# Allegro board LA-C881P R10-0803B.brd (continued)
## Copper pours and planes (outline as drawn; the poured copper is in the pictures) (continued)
B+ on TOP: 171.81,37.04 171.81,35.9 172.07,35.64 173.38,35.64 174.85,37.11 174.85,39.07 174.6,39.33 172.95,39.33 172.82,39.2 172.82,38.31 172.95,38.19 172.95,37.55 172.57,37.17 171.93,37.17
B+ on BOTTOM: 62.22,62.57 63.22,62.57 63.73,62.06 63.73,59.58 64.11,59.2 64.11,57.74 60.17,53.81 60.17,52.54 58.65,51.01 55.22,51.01 54.97,51.27 54.97,53.3 55.09,53.43 55.98,53.43 56.24,53.68 57.76,53.68 58.01,53.93 58.01,56.85 58.52,57.36 59.41,57.36 60.3,58.25 61.82,58.25 62.08,58.51 62.08,62.43
B+ on BOTTOM: 203.68,78.95 204.57,78.95 204.7,79.08 204.7,80.22 204.45,80.48 203.81,80.48 203.56,80.22 203.56,79.08
B+ on BOTTOM: 79.99,31.2 79.86,31.33 79.86,34.76 80.75,35.65 81.76,35.65 82.27,36.15 84.05,36.15 84.94,37.04 84.94,37.42 85.7,38.19 86.59,38.19 86.72,38.06 86.72,37.17 86.59,37.04 86.34,37.04 84.43,35.14 82.78,35.14 81.26,33.61 81.26,31.33 81.13,31.2
B+ on IN2: 65.38,52.03 65.38,50.89 72.87,43.39 72.87,40.6 78.97,34.5 80.49,34.5 81.13,33.87 81.13,31.33 80.62,30.82 76.68,30.82 70.21,37.3 60.43,37.3 53.95,43.77 53.95,50.5 55.09,51.65 55.09,52.54 58.52,55.97 59.41,55.97 59.67,55.71 59.67,53.04 60.3,52.41 65,52.41
B+ on IN2: 195.17,14.94 189.33,14.94 188.13,16.15 184.13,16.15 180.32,19.96 179.24,19.96 178.73,19.45 176.44,19.45 175.74,20.15 175.74,21.93 176,22.18 185.46,22.18 187.11,20.53 191.05,20.53 192.95,18.63 195.43,18.63 195.68,18.37 195.68,15.45
B+ on IN2: 173.08,35.52 173.71,35.52 174.09,35.9 174.09,36.41 174.35,36.66 174.73,36.66 174.98,36.92 174.98,37.42 175.87,38.31 175.87,43.27 176.89,44.28 180.19,44.28 181.33,45.42 181.33,51.39 180.57,52.16 179.05,52.16 177.83,50.94 177.83,47.15 178.03,46.95 178.03,46.31 177.78,46.06 175.16,46.06 173.53,44.43 173.53,39.66 172.7,38.82 172.7,35.9
B+ on IN3: outline of 87 points within 159.61,15.83 176.63,37.7
B+ on IN3: 69.57,41.87 81.51,41.87 84.24,39.13 84.24,37.87 87.46,34.65 88.73,34.65 93.45,29.93 93.45,28.15 93.57,28.03 93.57,23.58 95.99,21.17 95.99,17.48 95.73,17.23 94.84,17.23 94.46,16.85 83.29,16.85 80.62,19.52 80.62,30.18 80.18,30.63 76.49,30.63 69.44,37.68 69.44,41.74
B+ on IN3: 191.49,50.76 193.42,52.69 196.22,52.69 196.95,53.43 196.95,61.3 196.44,61.81 196.44,74.51 196.95,75.02 198.48,75.02 199.24,74.25 199.24,52.41 198.25,51.42 193.98,51.42 190.53,47.96 188.7,47.96 187.81,48.85 182.22,48.85 180.82,50.25 180.44,50.25 179.55,51.14 179.55,51.77 180.06,52.28 181.46,52.28 182.6,51.14 188.57,51.14 188.95,50.76
B+ on IN4: 100.12,18.42 163.09,18.42 163.42,18.08 163.42,17.55 161.67,15.8 92.97,15.8 92.61,16.16 92.61,17.33 93.15,17.87 99.56,17.87
B+ on GND3: 166.07,14.44 165.56,14.94 100.92,14.94 99.65,16.21 93.68,16.21 93.19,16.7 93.19,18.01 94.44,19.26 99.82,19.26 101.09,17.99 115.9,17.99 116.41,18.5 117.09,18.5 117.6,17.99 163.19,17.99 163.45,17.74 164.16,17.74 164.42,17.99 174.75,17.99 175.11,17.63 175.11,15.56 174.49,14.94 166.75,14.94 166.24,14.44
B+_1.0V on TOP: 197.52,64.29 197.59,64.22 197.59,63.33 197.46,63.2 196.19,63.2 195.68,62.7 194.29,62.7 194.03,62.95 194.03,64.22 194.1,64.29
B+_1.0V on BOTTOM: 200.1,64.86 200.1,63.99 198.12,63.99 197.33,63.2 196.57,63.2 196.06,62.7 194.21,62.7 194.03,62.87 194.03,64.6 194.29,64.86 195.58,64.86 195.58,65.24 196.09,65.74 197.43,65.74 198.32,64.86
B+_3V on TOP (solid shape): 94.21,24.09 94.21,22.44 93.93,22.16 92.35,22.16 91.89,22.62 91.38,22.62 90.94,22.18 89.48,22.18 89.48,22.72 89.13,23.07 89.13,23.58 89.76,24.22 94.08,24.22
B+_3V on BOTTOM: 93.86,24.44 94.21,24.09 94.21,22.44 93.93,22.16 92.35,22.16 91.82,22.69 91.24,22.69 90.8,22.25 90.8,21.93 90.74,21.87 89.27,21.87 89.2,21.93 89.2,23 89.13,23.07 89.13,23.32 90.25,24.44
B+_3V on IN2: 92.3,22.56 89.13,22.56 88.88,22.82 88.88,23.33 89.13,23.58 89.64,23.58 90.27,24.22 92.3,24.22 92.43,24.09 92.43,22.69
B+_5V on TOP: 62.97,44.03 63.09,43.9 64.62,43.9 65.13,43.39 69.3,43.39 69.41,43.49 69.41,43.77 69.52,43.89 71.1,43.89 71.22,44.01 71.22,44.92 70.97,45.17 63.22,45.17 62.97,44.92
B+_5V on BOTTOM: 62.91,44.42 62.91,43.65 62.98,43.58 64.55,43.58 64.75,43.77 65.63,43.77 66.02,43.39 69.28,43.39 69.43,43.54 69.43,43.77 69.52,43.86 71.06,43.86 71.22,44.03 71.22,44.92 70.97,45.17 67.41,45.17 67.16,45.42 63.02,45.42 62.84,45.25 62.84,44.49
BATBTN# on TOP: 3.02,24.47 4.55,24.47 4.67,24.34 4.67,21.68 4.29,21.29 4.29,20.53 4.42,20.41 5.44,20.41 5.56,20.28 5.56,18.5 5.44,18.37 3.02,18.37 2.77,18.63 2.77,21.04 2.9,21.17 2.9,24.34
BQ24777_REGN on BOTTOM: 44.69,29.81 44.93,30.06 44.93,31.2 45.82,32.09 45.82,32.6 45.95,32.72 46.97,32.72 47.09,32.6 47.09,32.34 46.71,31.96 46.71,30.82 46.46,30.57 45.57,30.57 45.31,30.31 45.31,30.06 44.87,29.61 43.36,29.61 43.31,29.66 43.31,29.77 43.35,29.81
BST_3V on BOTTOM (solid shape): 89.03,23.23 89.03,21.95 88.95,21.88 88.8,21.88 88.62,22.06 87.86,22.06 87.73,22.18 87.73,23.08 88.06,23.4 88.85,23.4
BST_5V on BOTTOM: 62.71,43.66 62.71,45.24 62.58,45.37 62.06,45.37 61.95,45.26 61.95,43.77 62.14,43.58 62.64,43.58
CHAGER_SRC on TOP: 51.16,36.66 51.28,36.53 51.28,35.77 51.54,35.52 51.54,30.18 52.05,29.68 55.22,29.68 55.35,29.55 55.35,25.74 54.59,24.98 50.65,24.98 50.52,25.1 50.52,30.69 50.39,30.82 50.39,32.85 50.14,33.11 48.36,33.11 48.11,33.36 48.11,35.9 48.39,36.18 49.35,36.18 49.84,36.66
CHAGER_SRC on BOTTOM: 50.78,36.66 50.9,36.53 50.9,35.9 51.03,35.77 51.28,35.77 51.54,35.52 51.54,30.18 52.05,29.68 55.22,29.68 55.35,29.55 55.35,25.74 54.59,24.98 50.65,24.98 50.52,25.1 50.52,30.69 50.39,30.82 50.39,32.85 50.14,33.11 48.36,33.11 48.11,33.36 48.11,36.41 48.36,36.66
CHG_BTS on BOTTOM (solid shape): 46.33,30.18 46.33,29.42 46.2,29.3 44.43,29.3 44.33,29.2 44.05,29.2 44.05,29.2 43.37,29.2 43.3,29.27 43.3,29.36 43.37,29.42 44.3,29.42 44.43,29.55 45.06,29.55 45.63,30.12 45.63,30.25 46.27,30.25
CHG_LGATE on BOTTOM: 43.32,30.22 44.21,30.22 44.3,30.31 44.3,30.95 44.43,31.07 44.68,31.07 44.81,30.95 44.81,30.13 44.6,29.93 44.25,29.93 44.19,30 43.62,30 43.61,29.99 43.31,29.99 43.28,30.02 43.28,30.18
CHG_LGATE on BOTTOM: 53.7,33.36 54.59,33.36 54.84,33.61 54.84,34.38 54.71,34.5 53.57,34.5 53.44,34.38 53.44,33.61
CHG_LGATE on IN1: 44.3,30.06 44.3,31.2 44.68,31.58 45.7,31.58 45.95,31.33 45.95,31.07 45.57,30.69 44.93,30.69 44.81,30.57 44.81,30.06 44.68,29.93 44.43,29.93
CHG_LGATE on IN1: 53.7,34.5 54.59,34.5 54.84,34.25 54.84,32.98 54.71,32.85 53.95,32.85 53.57,33.23 53.57,34.38
CHG_SW on BOTTOM (solid shape): 61.44,34.88 61.44,30.69 60.43,29.68 58.78,29.68 57.89,28.79 57.89,26.88 57.63,26.63 56.11,26.63 55.86,26.88 55.86,30.57 55.09,31.33 55.09,33.87 55.98,34.76 55.98,36.28 56.24,36.53 59.79,36.53
CHG_SW on BOTTOM: 43.36,28.61 44.34,28.61 44.43,28.53 45.44,28.53 45.57,28.66 45.57,28.91 45.7,29.04 46.71,29.04 46.84,28.91 46.84,28.08 46.76,28 46.4,28 46.3,27.9 44.68,27.9 44.43,28.15 44.43,28.28 44.3,28.41 43.36,28.41 43.31,28.46 43.31,28.56
CHG_SW on IN1: 47.73,28.79 47.73,28.15 47.47,27.9 46.33,27.9 46.08,28.15 46.08,28.91 46.2,29.04 47.47,29.04
CHG_SW on IN1: 58.65,34.76 58.52,34.63 57.89,34.63 57.63,34.88 57.63,36.25 57.78,36.4 58.53,36.4 58.65,36.27
CHG_UGATE on BOTTOM: 44.45,29.17 45.31,29.17 45.44,29.04 45.44,28.79 45.31,28.66 44.48,28.66 44.35,28.79 43.35,28.79 43.31,28.83 43.31,28.99 43.33,29.02 44.3,29.02
CHG_UGATE on BOTTOM: 57.13,26.12 56.24,26.12 55.98,25.87 55.98,24.85 56.11,24.72 57.25,24.72 57.38,24.85 57.38,25.87
CHG_UGATE on IN4: 44.43,28.66 45.31,28.66 45.44,28.79 45.44,28.91 45.7,29.17 46.2,29.17 46.46,29.42 46.46,30.18 46.33,30.31 45.31,30.31 44.3,29.3 44.3,28.79
CHG_UGATE on IN4: 57.25,24.72 57.38,24.85 57.38,25.49 56.79,26.08 54.82,26.08 54.5,25.76 54.5,25.05 54.83,24.72
CORE_SW on TOP: 83.82,62.24 83.82,64 84.14,64.32 85.26,64.32 86.83,65.89 89.74,65.89 90.27,65.36 90.27,63.59 90.15,63.46 89.76,63.46 89.64,63.33 89.64,62.57 89.76,62.44 90.15,62.44 90.27,62.32 90.27,60.79 89.43,59.95 88.16,59.95 87.99,60.13 87.99,61.65 87.83,61.81 84.25,61.81
CORE_SW on BOTTOM: 83.82,64.49 84.7,64.49 86.97,66.76 89,66.76 90.4,65.36 90.4,63.84 90.02,63.46 88.88,63.46 88.75,63.33 88.75,62.57 88.88,62.44 90.15,62.44 90.4,62.19 90.4,60.66 89.64,59.9 86.59,59.9 84.94,61.55 84.51,61.55 83.82,62.23
CORE_SW on IN1: 85.07,61.68 85.07,63.97 86.72,65.62 89.26,65.62 89.51,65.36 89.51,60.28 89.13,59.9 86.84,59.9
CPU_B+ on TOP: 80.24,56.6 80.62,56.6 80.75,56.47 80.75,53.17 81,52.92 81,51.52 80.87,51.39 79.99,51.39 79.86,51.52 79.86,52.54 79.48,52.92 78.33,52.92 77.95,53.3 77.95,54.31 78.59,54.95 78.59,55.46 78.84,55.71 79.86,55.71 80.11,55.97 80.11,56.47
CPU_B+ on TOP: 78.72,59.27 78.59,59.39 78.59,61.05 78.84,61.3 79.1,61.3 79.22,61.43 79.22,63.33 80.11,64.22 80.75,64.22 80.87,64.09 80.87,61.68 81.26,61.3 81.26,58.25 81.13,58.12 80.37,58.12 80.24,58.25 80.24,58.76 79.73,59.27
CPU_B+ on TOP: 79.99,48.73 80.49,48.73 80.62,48.6 80.62,45.42 80.49,45.3 79.99,45.3 79.73,45.04 79.73,43.9 79.48,43.65 79.48,39.96 79.22,39.71 76.05,39.71 75.67,40.09 75.67,44.41 75.79,44.54 76.56,44.54 76.94,44.92 76.94,47.46 77.45,47.96 79.22,47.96
CPU_B+ on BOTTOM: 81.18,45.6 81.18,48.4 80.18,48.4 79.48,49.11 79.48,49.87 81.18,51.58 81.18,56.03 79.92,56.03 79.73,56.22 79.73,57.62 80.11,58 81.13,58 81.23,58.09 81.23,64.49 80.02,64.49 79.48,63.95 79.48,60.92 77.7,59.14 77.7,58.57 76.94,57.81 76.94,44.92 76.56,44.54 73.9,44.54 73.47,44.11 73.47,40.3 74.19,39.58 75.16,39.58 75.67,39.07 75.67,36.53 76.05,36.15 78.46,36.15 79.22,36.92 79.22,43.65
GT_SW1 on BOTTOM (solid shape): 89.26,49.74 89.26,48.22 89,47.96 88.49,47.96 88.37,47.84 88.37,46.69 88.49,46.57 89,46.57 89.26,46.31 89.26,44.28 88.62,43.65 86.21,43.65 83.78,46.07 83.78,48.4 84.84,48.4 86.61,50.17 88.82,50.17
GT_SW1 on TOP: 84.94,48.47 86.59,50.12 88.88,50.12 89.26,49.74 89.26,44.28 89.13,44.15 86.08,44.15 84.94,45.3
GT_SW1 on IN1: 85.19,44.92 85.19,48.47 86.72,50 88.88,50 89.51,49.36 89.51,45.04 88.75,44.28 85.83,44.28
GT_SW2 on TOP: 83.92,54.82 83.92,55.84 84.68,56.6 85.45,56.6 86.72,57.87 89.13,57.87 89.38,57.62 89.38,52.41 89.26,52.28 84.81,52.28 84.43,52.66 84.43,54.31
GT_SW2 on BOTTOM: 84.87,56.03 83.78,56.03 83.78,53.69 85.19,52.28 89.26,52.28 89.38,52.41 89.38,53.93 89.26,54.06 87.73,54.06 87.48,54.31 87.48,55.58 87.61,55.71 89.26,55.71 89.38,55.84 89.38,57.62 89.13,57.87 86.72,57.87
GT_SW2 on IN1: 85.32,52.54 85.32,56.35 86.59,57.62 89.13,57.62 89.38,57.36 89.38,52.79 88.88,52.28 85.57,52.28
LX_1.0V on BOTTOM: 200.07,62.84 198.92,62.84 198.92,61.62 198.48,61.17 197.4,61.17 197.08,60.85 197.08,58.24 197.19,58.12 199.75,58.12 201.42,59.8 201.42,60.03 201.83,60.44 202.34,60.44 202.51,60.61 202.51,61.2 202.41,61.3 200.51,61.3 200.07,61.74
LX_1V_PRIM on BOTTOM: 87.33,30.24 88.44,30.24 88.91,29.77 91.06,29.77 91.67,29.16 91.67,28.03 91.54,27.9 91.03,27.9 90.53,27.39 90.53,27.01 90.4,26.88 89.51,26.88 89.38,27.01 89.38,27.52 89,27.9 88.62,27.9 88.49,28.03 88.49,29.17 88.18,29.49 87.32,29.49 87.26,29.55 87.26,30.17
LX_3V on TOP (solid shape): 85.67,22.54 85.67,22.08 85.95,21.8 86.72,21.8 86.84,21.68 86.84,19.64 86.59,19.39 83.29,19.39 82.91,19.77 82.91,22.69 82.93,22.72 84.02,22.72 84.05,22.74 85.47,22.74
LX_3V on BOTTOM (solid shape): 87.62,21.79 88.6,21.79 88.67,21.71 90.79,21.71 90.86,21.79 91.7,21.79 91.77,21.71 91.77,21.61 91.7,21.53 90.95,21.53 90.88,21.46 89.19,21.46 88.81,21.08 87.65,21.08 86.72,20.15 86.72,19.01 86.34,18.63 84.81,18.63 84.3,19.14 84.3,22.56 84.56,22.82 86.59,22.82
LX_5V on TOP (solid shape): 59.03,44.54 59.03,43.52 59.28,43.27 60.17,43.27 60.23,43.21 60.23,41.93 60.17,41.87 57.51,41.87 57.25,42.12 57.25,44.15 57.89,44.79 58.78,44.79
LX_5V on BOTTOM (solid shape): 61.2,43.5 62.37,43.5 62.42,43.45 64.6,43.45 64.66,43.5 65.41,43.5 65.48,43.43 65.48,43.32 65.41,43.25 64.61,43.25 64.53,43.18 62.5,43.18 62.46,43.14 62.46,42.88 62.38,42.8 60.98,42.8 60.81,42.63 60.81,40.39 60.58,40.17 57.68,40.17 57.25,40.6 57.25,43.87 58.17,44.79 59.92,44.79
LX_DDR on TOP (solid shape): 169.9,30.82 169.9,29.02 171.4,27.52 173.2,27.52 173.58,27.14 173.58,25.49 173.33,25.23 172.36,25.23 171.86,24.72 167.31,24.72 166.98,25.05 166.98,26.76 168.5,28.28 168.5,30.84 168.61,30.95 169.77,30.95
LX_PRIM on TOP: 197.72,75.02 198.85,75.02 198.92,74.95 198.92,74.34 198.84,74.27 197.98,74.27 197.71,74 197.71,72.86 197.46,72.6 195.68,72.6 195.56,72.48 195.56,71.59 195.43,71.46 194.79,71.46 194.67,71.59 194.67,73.62 195.05,74 196.7,74
LX_VCC_EDRAM on BOTTOM: 94.59,38.06 94.46,37.93 93.07,37.93 92.69,37.55 92.69,36.66 92.56,36.53 91.8,36.53 91.67,36.66 91.67,38.27 91.41,38.53 90.48,38.53 90.42,38.6 90.42,39.23 90.48,39.29 91.44,39.29 91.71,39.56 94.3,39.56 94.59,39.27
LX_VCCIO on TOP: 171.04,47.71 171.81,47.71 172.06,47.96 172.06,49.23 172.31,49.49 173.3,49.49 173.37,49.55 173.37,50.17 173.3,50.25 172.32,50.25 172.31,50.25 171.68,49.62 168.89,49.62 168.5,49.23 168.5,48.09 168.76,47.84 169.52,47.84 169.9,47.46 169.9,46.82 170.03,46.69 170.66,46.69 170.79,46.82 170.79,47.46
PBATT+_C on BOTTOM: 69.19,28.53 69.19,23.71 69.44,23.45 75.03,23.45 75.29,23.2 75.29,22.56 75.41,22.44 75.92,22.44 76.05,22.56 76.05,23.33 75.92,23.45 75.54,23.45 75.03,23.96 75.03,26.5 74.78,26.76 74.02,26.76 72.23,28.55 71.72,28.55 71.6,28.66 69.32,28.66
RING2 on TOP: 7.72,22.06 8.36,22.06 8.48,22.18 8.48,22.69 8.36,22.82 8.1,22.82 7.85,23.07 7.85,23.83 8.1,24.09 8.74,24.09 8.87,24.22 8.87,24.72 8.74,24.85 7.47,24.85 7.09,24.47 7.09,22.95 7.6,22.44 7.6,22.18
RING2 on IN2: 7.98,24.72 13.44,24.72 14.96,26.25 14.96,32.22 18.77,36.03 24.99,36.03 25.25,36.28 28.04,36.28 28.71,35.61 28.71,33.08 28.48,32.85 20.04,32.85 17.25,30.06 17.25,25.36 14.76,22.87 7.99,22.87 7.72,23.13 7.72,24.47
RING2_R on TOP: 5.94,22.82 6.2,22.82 6.58,22.44 6.58,22.06 6.71,21.93 8.61,21.93 10.14,23.45 13.69,23.45 14.96,24.72 14.96,28.03 15.22,28.28 16.87,28.28 16.99,28.15 16.99,27.26 16.61,26.88 16.23,26.88 15.98,26.63 15.98,23.83 13.31,21.17 5.18,21.17 5.06,21.29 5.06,22.69 5.56,23.2
SA_B+ on BOTTOM (solid shape): 70.71,62.95 70.71,62.57 70.59,62.44 70.08,62.44 69.95,62.32 69.95,61.43 69.7,61.17 67.29,61.17 67.03,61.43 66.01,61.43 65.85,61.26 64.25,61.26 64.11,61.4 64.11,62.44 64.52,62.85 67.34,62.85 67.39,62.8 67.86,62.8 68.07,63.01 70.66,63.01
SA_B+ on TOP: 69.38,61.05 66.14,61.05 65.63,61.55 65.63,62.57 65.89,62.82 67.34,62.82 67.41,62.75 67.69,62.75 67.77,62.82 69.62,62.82 69.66,62.78 70.25,62.78 70.4,62.63 70.4,62.38 69.76,61.74 69.76,61.43
SLEEVE on TOP: 28.01,34.23 27.87,34.38 27.63,34.37 27.54,34.37 27.44,34.27 27.44,33.5 27.68,33.26 27.68,32.33 27.73,32.28 27.97,32.28 28.01,32.32
SLEEVE on BOTTOM: 7.6,22.69 9.75,22.69 9.75,22.69 10.03,22.69 10.26,22.46 10.26,21.84 10.1,21.68 7.6,21.68 7.47,21.8 7.47,22.56
SLEEVE on IN3: 8.87,22.56 15.85,22.56 17.76,24.47 17.76,29.8 22.2,34.25 27.15,34.25 27.41,34.5 27.79,34.5 28.04,34.25 28.04,32.6 27.79,32.34 25.38,32.34 21.82,28.79 21.57,28.79 20.93,28.15 20.93,25.49 16.49,21.04 8.87,21.04 8.74,21.17 8.74,22.44
SLEEVE_R on TOP: 17.76,27.26 18.52,27.26 18.77,27.01 18.77,25.49 18.64,25.36 17.88,25.36 17.76,25.49 17.76,26.37 17.5,26.63 17.5,27.01
SLEEVE_R on BOTTOM: 7.34,25.99 5.94,25.99 5.44,25.49 5.44,22.95 5.56,22.82 8.1,22.82 8.23,22.95 8.23,24.34 7.6,24.98 7.6,25.74
SPK_L+_C on BOTTOM (solid shape): 26.65,17.36 26.65,16.6 26.52,16.47 24.49,16.47 23.98,15.96 22.45,15.96 22.2,16.21 22.2,16.85 22.58,17.23 22.96,17.23 23.22,17.48 26.52,17.48
SPK_L+_C on TOP: 23.98,17.48 23.98,16.09 23.72,15.83 22.2,15.83 21.95,16.09 21.95,17.36 21.49,17.81 21.49,18.65 21.64,18.8 23.27,18.8 23.34,18.88 23.34,20.38 23.37,20.41 24.23,20.41 24.36,20.28 24.36,17.87
SPK_L-_C on BOTTOM (solid shape): 26.77,15.96 26.77,15.58 26.65,15.45 25.25,15.45 24.61,14.82 24.61,13.93 24.36,13.67 23.47,13.67 23.22,13.93 23.22,14.69 24.74,16.21 26.52,16.21
SPK_L-_C on TOP: 22.2,15.58 23.98,15.58 24.49,16.09 24.49,17.48 25.25,18.25 25.25,19.52 24.99,19.77 24.99,20.28 25.12,20.41 26.01,20.41 26.14,20.28 26.14,17.74 25.63,17.23 25.63,15.45 24.49,14.31 22.2,14.31 22.07,14.44 22.07,15.45
SPK_OUT_L+ on TOP: 23.34,20.53 24.61,20.53 24.74,20.66 24.74,21.68 24.61,21.8 23.34,21.8 23.22,21.68 23.22,20.66
SPK_OUT_L+ on TOP: 27.52,27.07 27.57,27.02 27.57,25.02 27.05,24.5 26.83,24.5 26.7,24.62 26.7,24.82 27.33,25.45 27.33,27.02 27.39,27.07
SPK_OUT_L+ on IN1: 26.82,25 26.82,24.72 27.15,24.39 27.15,23.71 25.12,21.68 24.11,21.68 23.98,21.55 23.98,20.41 24.11,20.28 25.71,20.28 28.8,23.38 28.8,25.13 28.52,25.41 27.23,25.41
SPK_OUT_L- on TOP: 25.12,20.53 26.01,20.53 27.79,22.31 27.79,23.58 28.42,24.22 28.42,24.72 28.04,25.1 28.04,25.23 27.97,25.3 27.97,27.03 27.93,27.08 27.79,27.08 27.74,27.03 27.74,25.35 27.66,25.27 27.66,24.85 26.39,23.58 26.39,22.95 24.99,21.55 24.99,20.66
SPK_OUT_R+ on TOP: 29.57,24.49 29.57,23.33 29.31,23.07 29.31,21.21 29.37,21.15 30.57,21.15 30.59,21.17 30.59,24.66 30.35,24.9 29.67,24.9 29.66,24.91 29.62,24.91 28.82,25.71 28.82,25.99 28.83,26 28.83,26.99 28.74,27.08 28.61,27.08 28.53,27 28.53,25.52 29.01,25.04 29.01,25.04
SPK_OUT_R- on TOP: 28.55,24.72 28.55,24.09 28.04,23.58 28.04,20.66 28.17,20.53 28.93,20.53 29.06,20.66 29.06,23.07 29.44,23.45 29.44,24.47 28.37,25.53 28.37,27.01 28.31,27.07 28.2,27.07 28.14,27.01 28.14,25.13
SPK_R+_C on BOTTOM (solid shape): 29.72,14.92 29.72,13.95 29.08,13.32 25.35,13.32 24.99,13.67 24.99,14.13 25.2,14.33 28.19,14.33 28.85,14.99 29.64,14.99
SPK_R+_C on TOP: 28.42,14.44 29.82,14.44 30.07,14.69 30.07,15.96 30.96,16.85 30.96,20.53 30.58,20.91 29.82,20.91 29.69,20.79 29.69,20.41 29.95,20.15 29.95,19.39 30.07,19.26 30.07,18.25 28.17,16.34 28.17,14.69
SPK_R-_C on BOTTOM (solid shape): 27.86,14.92 27.86,14.66 27.71,14.51 25.17,14.51 24.99,14.69 24.99,14.94 25.2,15.15 27.64,15.15
SPK_R-_C on TOP: 27.28,21.55 27.79,21.55 27.92,21.42 27.92,19.26 27.28,18.63 27.28,16.98 27.66,16.6 27.66,14.69 27.41,14.44 26.39,14.44 26.14,14.69 26.14,17.36 26.26,17.48 26.26,20.53
SW_1.8VA on TOP: 169.52,78.06 171.4,78.06 171.73,77.73 171.73,76.62 172.19,76.16 172.19,74.63 172.06,74.51 171.04,74.51 170.92,74.38 169.39,74.38 169.27,74.51 169.27,77.81
SW_1.8VU on TOP: 164.44,44.66 164.44,41.36 164.82,40.98 165.71,40.98 165.84,41.11 165.84,41.49 166.11,41.76 167.44,41.76 167.49,41.8 167.49,43.01 167.01,43.49 167.01,44.88 166.84,45.04 164.82,45.04
TBT_SVR_IND on TOP: 35.02,49.19 36.12,49.19 36.55,49.62 36.55,53.01 37.01,53.47 37.33,53.78 37.68,53.78 37.68,53.78 38.17,53.78 38.96,54.57 38.96,55.58 38.84,55.71 38.71,55.71 38.58,55.84 38.58,56.09 38.46,56.22 38.33,56.22 38.2,56.09 38.2,54.82 37.95,54.57 36.81,54.57 36.4,54.16 35.14,54.16 34.77,53.8 34.77,49.43
TBT_VBUS on TOP: 17.76,53.43 17.88,53.3 20.68,53.3 20.8,53.43 20.8,54.95 20.55,55.2 19.28,55.2 19.03,55.46 19.03,56.22 18.77,56.47 18.01,56.47 17.76,56.22
TBT_VBUS on BOTTOM: 48.49,75.4 48.62,75.27 48.62,74 48.49,73.87 45.24,73.87 44.31,74.8 44.31,75.28 45.09,76.06 46.18,76.06 46.33,75.9 46.33,75.42 46.36,75.4
TBT_VBUS on BOTTOM: 18.96,57.04 20.1,57.04 20.36,56.79 20.36,54.82 20.1,54.57 18.71,54.57 17.88,55.39 17.12,55.39 16.8,55.71 16.8,56.79 17.06,57.04 17.63,57.04 17.95,56.73 18.64,56.73
TBT_VBUS on VCC: 8.84,54.44 5.35,57.94 5.71,58.04 5.87,58.39 5.87,59.19 5.56,59.62 5.06,59.47 5.06,62.11 5.56,61.96 5.86,62.39 5.86,63.19 5.56,63.62 5.06,63.46 5.06,66.65 7.12,67.56 8.1,68.4 8.47,69.64 8.47,70.12 8.98,71.34 10.2,71.85 14.5,71.85 16.11,72.52 16.77,74.12 16.77,79.23 44,79.23 45.15,79.66 45.75,80.73 47.73,80.73 47.73,70.68 44.7,67.65 24,67.65 21.57,65.21 21.57,55.44 20.57,54.44 ; 2 cut-outs
TBT_VBUS_L on TOP: 19.53,58.17 20.16,58.8 20.74,58.8 21.29,59.36 21.29,59.45 21.51,59.67 21.69,59.67 21.87,59.85 21.87,60.03 21.95,60.11 22.07,60.11 22.63,59.55 22.63,59.42 22.28,59.06 22.27,59.06 21.36,58.15 21.18,58.15 21.16,58.13 20.86,58.13 20.73,58 20.73,55.63 20.55,55.46 19.41,55.46 19.28,55.58 19.28,56.47 19.53,56.73
N15438182 on TOP: 43.16,25.1 43.16,27.26 43.79,27.9 45.06,27.9 45.31,27.64 45.31,26.63 44.93,26.25 44.93,25.1 44.81,24.98 43.28,24.98
N15438182 on BOTTOM: 43.35,28.22 44.17,28.22 44.2,28.19 44.2,28 44.43,27.77 46.08,27.77 46.2,27.64 46.2,26.12 46.08,25.99 44.43,25.99 43.28,27.14 43.28,28.15
N52893865 on TOP: 172.06,17.99 173.2,17.99 173.84,17.36 174.22,17.36 174.47,17.61 174.47,18.27 174.19,18.55 174.19,19.5 174.05,19.64 173.46,19.64 172.7,18.88 172.17,18.88 172,18.7 172,18.06
N52893895 on TOP: 168.48,19.01 170.46,19.01 170.6,18.86 170.6,18.06 170.54,17.99 169.77,17.99 169.65,18.12 168.38,18.12 168.25,18.25 168.25,18.78
N52922903 on TOP: 178.92,31.84 178.98,31.77 178.98,30.63 178.54,30.18 178.54,28.79 178.41,28.66 177.27,28.66 177.14,28.79 177.14,30.82 178.16,31.84
N52922958 on TOP: 180.37,31.89 181,31.89 181.08,31.81 181.08,30.39 181.23,30.23 182.06,30.23 182.09,30.2 182.96,30.2 183.13,30.03 183.13,29.33 182.96,29.17 180.44,29.17 180.32,29.3 180.32,31.84
N52925836 on TOP: 48.24,22.18 49.76,22.18 50.27,21.68 50.27,20.91 50.19,20.84 48.79,20.84 48.59,21.04 48.24,21.04 48.16,21.12 48.16,22.11
N52925896 on TOP: 48.97,19.52 50.14,19.52 50.29,19.36 50.29,18.75 50.14,18.6 50.14,17.23 49.51,16.6 48.79,16.6 47.7,17.69 47.7,18.91 48.01,19.21 48.67,19.21
N52930519 on TOP: 37.69,44.03 38.58,44.03 38.84,44.28 40.23,44.28 40.36,44.15 40.36,42.25 40.23,42.12 39.22,42.12 38.2,43.14 37.69,43.14 37.57,43.27 37.57,43.9
N52930575 on TOP: 35.03,45.55 36.3,45.55 36.42,45.42 36.42,44.66 36.25,44.48 36.25,43.21 36.17,43.14 35.41,43.14 35.15,43.39 35.15,44.41 34.9,44.66 34.9,45.42
N52934489 on TOP: 30.2,41.23 32.36,41.23 32.49,41.11 32.49,40.6 32.36,40.47 30.2,40.47 29.82,40.85 28.68,40.85 28.42,41.11 28.42,41.74 28.68,42 29.44,42
N52934545 on TOP: 33.88,41.23 34.65,41.23 34.77,41.11 34.77,39.2 34.65,39.07 33.88,39.07 33.76,39.2 33.76,41.11
N55952897 on TOP: 169.51,43.01 170.66,43.01 170.92,42.76 170.92,42.25 171.3,41.87 173.2,41.87 173.84,41.23 173.84,39.96 173.71,39.84 171.04,39.84 170.79,40.09 170.79,41.36 170.39,41.76 169.5,41.76 169.45,41.81 169.45,42.95
N56035968 on TOP (solid shape): 176.76,80.6 176.76,78.83 177.27,78.32 177.27,76.67 177.01,76.41 177.01,75.02 176.76,74.76 176.25,74.76 176.14,74.65 174.19,74.65 174.15,74.69 174.15,75.84 174.21,75.9 175.11,75.9 175.49,76.29 175.49,79.59 175.51,79.61 175.51,80.68 175.62,80.78 176.58,80.78
N56041706 on TOP: 170.41,34.76 170.84,34.32 170.84,33.79 170.15,33.1 170.15,31.12 169.74,31.12 169.74,33.21 169.09,33.87 168.76,33.87 168.63,33.99 168.63,37.02 168.71,37.09 169.24,37.09 169.32,37.02 170.82,37.02 170.93,36.9 170.93,36.03 170.41,35.51
N56704068 on BOTTOM: 34.01,79.21 35.15,79.21 35.15,77.56 34.65,77.05 34.65,76.54 34.52,76.41 34.27,76.41 33.88,76.79 33.88,79.08
N56715138 on BOTTOM: 48.24,80.6 50.65,80.6 50.78,80.48 50.78,78.32 50.65,78.19 48.74,78.19 48.49,78.44 48.11,78.44 47.98,78.57 47.98,80.35
N56728350 on BOTTOM: 53.95,55.2 55.73,55.2 55.79,55.14 55.79,54.82 55.54,54.57 55.54,53.81 55.41,53.68 54.97,53.68 54.84,53.55 54.84,52.03 54.59,51.77 54.2,51.77 53.82,51.39 52.43,51.39 52.05,51.77 52.05,52.54 52.37,52.86 53.03,52.86 53.54,53.37 53.54,54.79
N56744237 on BOTTOM: 41.38,79.21 44.17,79.21 44.43,78.95 44.43,77.43 44.3,77.3 43.79,77.3 43.54,77.05 43.53,77.05 43.38,76.9 41.19,76.9 41.13,76.96 41.13,77.41 41.19,77.47 41.29,77.47 41.38,77.56 42.65,77.56 42.84,77.75 42.84,78.01 42.65,78.2 41.16,78.2 41.12,78.24 41.12,78.95
N56767142 on BOTTOM: 89,17.48 90.4,17.48 90.53,17.36 90.53,16.72 90.4,16.6 89,16.6 88.88,16.72 88.88,17.36
N57177583 on TOP: 154.66,75.9 154.79,75.78 154.79,74.51 154.53,74.25 153.9,74.25 153.52,74.63 152.88,74.63 152.76,74.76 152.76,75.78 152.76,75.78 152.76,76.74 152.93,76.91 153.55,76.91 153.69,76.78 153.69,75.9
N57177931 on TOP: 161.9,48.35 162.15,48.35 162.41,48.09 162.41,46.82 162.28,46.69 161.9,46.69 161.65,46.95 160.63,46.95 160.5,47.08 160.5,48.09 160.63,48.22 161.77,48.22
N57178338 on TOP: 161.77,66.89 162.79,66.89 163.17,67.27 163.68,67.27 163.81,67.14 163.81,65.11 163.55,64.86 161.77,64.86 161.65,64.98 161.65,66.76
N57965459 on BOTTOM: 55.51,60.12 55.95,60.12 56.11,59.97 56.11,57.55 56.49,57.17 56.49,55.65 56.3,55.46 53.95,55.46 53.53,55.88 53.53,59.99 53.68,60.14 54.6,60.14 54.65,60.09 54.65,58.57 54.97,58.25 55.22,58.25 55.47,58.51 55.47,60.09
N60799730 on TOP (solid shape): 62.08,64.73 62.84,64.73 63.09,64.47 63.09,63.59 63,63.49 62.43,63.49 62.03,63.89 61.04,63.89 60.94,63.99 60.94,64.73 61.06,64.86 61.95,64.86
N60799730 on BOTTOM (solid shape): 73.89,68.03 73.89,65.36 74.27,64.98 74.27,62.95 74.14,62.82 73.7,62.82 73.7,62.06 73.83,61.93 74.14,61.93 74.27,61.81 74.27,60.98 74.14,60.85 71.73,60.85 71.48,61.11 71.48,62.7 70.84,63.33 68.05,63.33 68.05,64.35 70.84,64.35 72.37,65.87 72.37,68.03 72.49,68.16 73.76,68.16
N60799730 on IN3: 62.21,63.59 61.95,63.84 61.95,67.27 63.48,68.79 71.98,68.79 73.76,67.01 73.76,65.49 73.51,65.24 72.75,65.24 72.49,65.49 72.49,66.63 71.35,67.78 65.13,67.78 63.09,65.74 63.09,63.84 62.84,63.59
N60799760 on BOTTOM (solid shape): 71.22,62.06 71.22,61.43 70.97,61.17 70.33,61.17 70.09,61.42 70.09,62.17 70.2,62.28 71.01,62.28
N60799760 on IN3 (solid shape): 63.09,62.19 63.09,60.16 62.84,59.9 62.46,59.9 62.21,60.16 62.21,62.19 62.46,62.44 62.84,62.44
N60799760 on IN3 (solid shape): 71.22,62.06 71.22,61.43 70.97,61.17 70.33,61.17 69.71,61.79 69.33,61.79 69.32,61.81 69.32,62.44 69.57,62.7 70.59,62.7
N60799760 on TOP: 62.34,62.07 63.02,62.07 63.09,62 63.09,60.31 62.83,60.05 62.58,60.05 62.21,60.42 62.21,61.93
N60799765 on TOP (solid shape): 65.38,64.35 65.38,63.71 65.15,63.49 64.4,63.49 64.33,63.55 64.33,64.44 64.49,64.6 65.13,64.6
N60799765 on BOTTOM (solid shape): 71.1,65.36 71.1,64.98 70.64,64.53 70.15,64.53 70.08,64.6 70.08,65.74 70.21,65.87 70.59,65.87
N60799765 on IN3 (solid shape): 71.1,66.4 71.1,64.98 70.64,64.52 70.16,64.52 70.08,64.6 70.08,66.4 70.26,66.58 70.92,66.58
N60799765 on IN3 (solid shape): 65.51,65.08 65.51,64.73 65.38,64.6 65.38,63.71 65.15,63.48 64.41,63.48 64.34,63.56 64.34,64.45 64.49,64.6 64.49,65.11 64.67,65.29 65.3,65.29
N60799776 on TOP (solid shape): 63.59,62 63.59,61.25 63.73,61.11 63.73,60.12 63.67,60.05 63.26,60.05 63.22,60.09 63.22,61.07 63.34,61.19 63.34,62.02 63.4,62.07 63.52,62.07
N62098363 on TOP: 200.97,41.31 202.34,41.31 202.41,41.23 202.41,37.65 202.36,37.6 200.36,37.6 200.33,37.63 200.33,39 200.84,39.51 200.84,41.18
N65247919 on TOP: 36.46,34.36 35.85,34.36 35.75,34.46 35.75,36.36 36.03,36.64 36.77,36.64 37.1,36.31 37.38,36.31 37.45,36.23 37.45,35.77 37.28,35.59 36.67,35.59 36.51,35.44 36.51,34.41
N119009632 on BOTTOM: 28.93,76.03 29.06,76.16 30.58,76.16 31.34,75.4 31.85,75.4 31.98,75.27 31.98,74.89 31.97,74.88 31.97,74.63 31.85,74.5 30.69,74.5 30.69,74.51 29.31,74.51 28.93,74.89

Small or netless copper shapes (teardrops, artwork), in the pictures only: 18 on TOP, 16 on BOTTOM, 5 on IN2, 1 on IN3, 1 on IN4

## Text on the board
Ref Des/Silkscreen Bottom: RTC | Battery | DC-IN | Speaker | WLAN+BT | Board | Keyboard | Camera | Touch | Screen | Fan | Touch Pad | LCD | IO Board | UART | H11 | H14 | H16 | H15 | H10 | H6 | H17
User.Comments: LA-C881P | AAZ80 | 2015-08-03 | 2016-08-03 | Minjia_Cai | 1.0(A00)
User.39: FIGURE | SIZE | 8.0 | 10.0 | 16.0 | 26.0 | 31.0 | 79.0 | 130.0 | 30.0 | 40.0 | 43.0 | 63.0 | 71.0 | 51.0x31.0 | 55.0x24.0 | 63.0x24.0 | 75.0x31.0 | 126.0x31.0 | 37.0x30.0 | 91.0x71.0 | DRILL CHART: TOP to BOTTOM | ALL UNITS ARE IN MILS | TOLERANCE | +3.0/-3.0 | +2.0/-2.0 | PLATED | NON-PLATED | QTY | 4402 | 528 | 59 | 12 | 2 | 9 | 8 | 7 | 1 | 4
User.40: trace Width | 5.6 | 4.6 | 3.2 | 3.5 | 5 | Width/Space | 4.5/3.5 | 4.8/4 | 3.6/4 | 4/4.8 | 5/5 | Single end | 4 | 4/4.4 | Diff | L4/L6 | 6.4/3.5 | L3 | L8 | L1-TOP | L2-GND1 | L3-IN1 | L4-GND2 | L5-IN2 | L6-IN3 | L7-VCC | L8-IN4 | L9-GND3 | L10-BOT | HR_1_0mm-10L(3mil core 1oz)-stack-up-150429.pdf | LAYER | NAME | STACKUP: 10 LAYER | 40 ohm | 50 ohm | 75 ohm | THICKNESS=1.0mm | 85 ohm | 90 ohm | ref
